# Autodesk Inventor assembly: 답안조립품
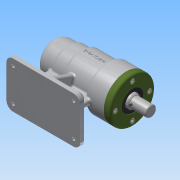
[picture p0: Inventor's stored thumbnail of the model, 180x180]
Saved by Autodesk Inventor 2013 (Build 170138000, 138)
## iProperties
Created: 2016-06
Part Number: 답안조립품
Document SubType Name: Assembly
Designer: user
Author: user
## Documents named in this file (12)
- C:\Users\user\Desktop\460608V1012\답안조립품.iam
- C:\Users\user\Desktop\460608V1012\본체.ipt
- C:\Users\user\Desktop\460608V1012\공용부품\V벨트풀리.ipt
- C:\Users\user\Desktop\460608V1012\공용부품\멈춤나사 M3x8.ipt
- C:\Users\user\Desktop\460608V1012\공용부품\베어링 6004.ipt
- C:\Users\user\Desktop\460608V1012\공용부품\베어링 51202.ipt
- C:\Users\user\Desktop\460608V1012\공용부품\볼트 M4 x 12.ipt
- C:\Users\user\Desktop\460608V1012\공용부품\어댑터슬리브.ipt
- C:\Users\user\Desktop\460608V1012\공용부품\오일 실.ipt
- C:\Users\user\Desktop\460608V1012\공용부품\축.ipt
- C:\Users\user\Desktop\460608V1012\공용부품\커버.ipt
- C:\Users\user\Desktop\460608V1012\공용부품\키 5 x 5 x 16.ipt
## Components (6 placed, 2 different names)
1. V벨트풀리:1 — 각도:2
2. ISO 4762 M4 x 12:2
3. ISO 4762 M4 x 12:1 — 각도:3
4. ISO 4762 M4 x 12:3
5. ISO 4762 M4 x 12:4
6. ISO 4762 M4 x 12:5
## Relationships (2: Angle 2)
- 각도:2 [Angle]: V벨트풀리:1
- 각도:3 [Angle]: ISO 4762 M4 x 12:1
